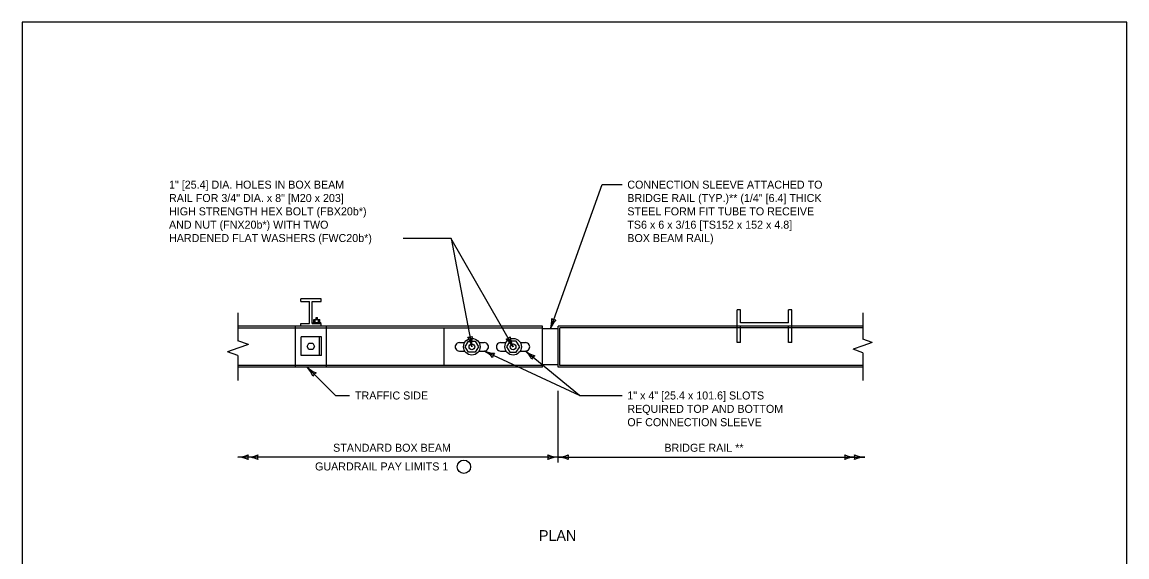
# Model space of a CAD drawing. Extents: x 49991.4 to 50021, y 49987.6 to 50011.4.
# Drawn here: x 50000.34 to 50008.61, y 50007.26 to 50011.26 of the extents above; entities that cross this region are included whole.
import ezdxf

# ---------------------------------------------------------------- set-up
doc = ezdxf.new("R2010")
doc.units = 0
for name, color, linetype in [('Level 1', 7, 'Continuous'), ('Level 2', 7, 'Continuous'), ('Level 3', 7, 'Continuous'), ('Level 4', 7, 'Continuous'), ('Level 6', 7, 'Continuous')]:
    doc.layers.add(name, color=color, linetype=linetype)

msp = doc.modelspace()

# ---------------------------------------------------------------- linework, layer by layer
at = {"layer": 'Level 1'}
for p, q in [((50002.5774, 50009.1903), (50002.4235, 50009.1903)), ((50002.4235, 50009.1702), (50002.4235, 50009.1903)), ((50002.4235, 50009.1702), (50002.4895, 50009.1702)), ((50002.4895, 50009.0047), (50002.4895, 50009.1702)), ((50002.5104, 50009.0047), (50002.5104, 50009.1702)), ((50002.5104, 50009.1702), (50002.5774, 50009.1702)), ((50002.5774, 50009.1702), (50002.5774, 50009.1903)), ((50005.6941, 50008.9846), (50005.6941, 50009.1075)), ((50005.7186, 50009.1075), (50005.6941, 50009.1075)), ((50005.7186, 50009.0095), (50005.7186, 50009.1075)), ((50006.0786, 50009.0095), (50006.0786, 50009.1075)), ((50006.103, 50009.1075), (50006.0786, 50009.1075)), ((50006.103, 50008.9846), (50006.103, 50009.1075)), ((50004.2346, 50008.9846), (50001.9531, 50008.9846)), ((50002.4235, 50009.0047), (50002.4895, 50009.0047)), ((50002.4235, 50008.9846), (50002.4235, 50009.0047)), ((50002.5104, 50009.0047), (50002.5774, 50009.0047)), ((50002.5161, 50009.0047), (50002.5161, 50009.0128)), ((50002.5161, 50009.0128), (50002.5741, 50009.0128)), ((50002.523, 50009.0338), (50002.5656, 50009.0338)), ((50002.523, 50009.0128), (50002.523, 50009.0338)), ((50002.533, 50009.0128), (50002.533, 50009.0338)), ((50002.5387, 50009.049), (50002.5504, 50009.049)), ((50002.5387, 50009.0338), (50002.5387, 50009.049)), ((50002.5504, 50009.0338), (50002.5504, 50009.049)), ((50002.5564, 50009.0128), (50002.5564, 50009.0338)), ((50002.5656, 50009.0128), (50002.5656, 50009.0338)), ((50002.5741, 50009.0047), (50002.5741, 50009.0128)), ((50002.5774, 50008.9846), (50002.5774, 50009.0047)), ((50004.2346, 50008.6768), (50004.2346, 50008.9846)), ((50004.3525, 50008.6768), (50004.3539, 50008.9846)), ((50006.6354, 50008.9846), (50004.3539, 50008.9846)), ((50006.0786, 50009.0095), (50005.7186, 50009.0095)), ((50002.5788, 50008.9059), (50002.4264, 50008.9059)), ((50002.4264, 50008.7655), (50002.4264, 50008.9059)), ((50002.5635, 50008.7655), (50002.5635, 50008.9059)), ((50002.5788, 50008.7655), (50002.5788, 50008.9059)), ((50004.3539, 50008.966), (50004.2346, 50008.966)), ((50002.5788, 50008.7655), (50002.4264, 50008.7655)), ((50004.2346, 50008.6768), (50001.9531, 50008.6768)), ((50004.3526, 50008.6953), (50004.2346, 50008.6953)), ((50006.6354, 50008.6768), (50004.3525, 50008.6768))]:
    msp.add_line(p, q, dxfattribs=at)
for points in [[(50008.6146, 50011.2628), (50000.3356, 50011.2628), (50000.3356, 50000.0624), (50008.6146, 50000.0624)], [(50002.5146, 50008.8109), (50002.4852, 50008.8109), (50002.4729, 50008.8331), (50002.4852, 50008.857), (50002.5146, 50008.857), (50002.5272, 50008.8331)], [(50003.7297, 50008.8724), (50003.7557, 50008.8304), (50003.7297, 50008.7898), (50003.6816, 50008.7898), (50003.6556, 50008.8304), (50003.6816, 50008.8724)], [(50003.9895, 50008.8724), (50003.9645, 50008.8304), (50003.9895, 50008.7898), (50004.039, 50008.7898), (50004.0645, 50008.8304), (50004.039, 50008.8724)]]:
    msp.add_lwpolyline(points, close=True, dxfattribs=at)
for centre, radius in [((50003.7057, 50008.8306), 0.0619), ((50004.0154, 50008.8306), 0.0619), ((50003.7061, 50008.8302), 0.0214), ((50004.015, 50008.8302), 0.0214)]:
    msp.add_circle(centre, radius, dxfattribs=at)
at = {"layer": 'Level 2'}
msp.add_circle((50003.6464, 50007.9312), 0.05, dxfattribs=at)
at = {"layer": 'Level 3'}
for p, q in [((50004.2943, 50008.966), (50004.6826, 50010.045)), ((50004.6826, 50010.045), (50004.8311, 50010.045)), ((50003.191, 50009.645), (50003.5487, 50009.645)), ((50004.015, 50008.8302), (50003.5491, 50009.6448)), ((50003.5501, 50009.6421), (50003.7061, 50008.8302)), ((50004.5119, 50008.4655), (50003.799, 50008.7984)), ((50004.5119, 50008.4655), (50004.1074, 50008.7984)), ((50002.4723, 50008.6768), (50002.6847, 50008.4655)), ((50004.3525, 50007.964), (50004.3525, 50008.4999)), ((50002.6847, 50008.4655), (50002.7902, 50008.4655)), ((50004.5119, 50008.4655), (50004.8311, 50008.4655)), ((50004.3525, 50008.004), (50001.9531, 50008.004)), ((50004.3525, 50008.004), (50006.6505, 50008.004))]:
    msp.add_line(p, q, dxfattribs=at)
for centre, radius, start, end in [((50004.0714, 50009.034), 0.233, 343.03502, 2.28487), ((50004.5002, 50008.8822), 0.2223, 137.66372, 157.84723), ((50004.3377, 50009.0866), 0.0548, 232.34653, 268.06889), ((50003.6819, 50008.9561), 0.0548, 263.01724, 298.7396), ((50003.4798, 50008.775), 0.233, 13.70573, 32.95558), ((50003.926, 50008.8631), 0.2223, 168.33443, 188.51794), ((50003.9513, 50008.9415), 0.0548, 281.90701, 317.62937), ((50003.8187, 50008.7047), 0.233, 32.5955, 51.84535), ((50004.2124, 50008.9325), 0.2223, 187.2242, 207.40771), ((50003.6968, 50008.601), 0.2223, 42.42587, 62.60938), ((50003.8871, 50009.0141), 0.233, 247.79717, 267.04702), ((50003.6968, 50008.601), 0.2223, 42.42587, 62.60938), ((50003.8871, 50009.0141), 0.233, 247.79717, 267.04702), ((50003.9152, 50008.7441), 0.0548, 137.10868, 172.83104), ((50003.9152, 50008.7441), 0.0548, 137.10868, 172.83104), ((50003.9592, 50008.6327), 0.2223, 28.00079, 48.1843), ((50004.2464, 50008.9854), 0.233, 233.37209, 252.62194), ((50004.2064, 50008.7169), 0.0548, 122.6836, 158.40596), ((50002.3091, 50008.5258), 0.2223, 22.61055, 42.79406), ((50002.6282, 50008.8499), 0.233, 227.98185, 247.2317), ((50002.5632, 50008.5864), 0.0548, 117.29336, 153.01572), ((50001.9416, 50008.2367), 0.233, 272.82731, 292.07716), ((50001.9439, 50007.7819), 0.2223, 67.45601, 87.63952), ((50002.015, 50008.2367), 0.233, 272.82731, 292.07716), ((50002.0813, 50008.004), 0.0548, 162.13882, 197.86118), ((50002.0174, 50007.7819), 0.2223, 67.45601, 87.63952), ((50002.1548, 50008.004), 0.0548, 162.13882, 197.86118), ((50004.3617, 50008.2261), 0.2223, 247.45601, 267.63952), ((50004.2243, 50008.004), 0.0548, 342.13882, 17.86118), ((50004.364, 50007.7713), 0.233, 92.82731, 112.07716), ((50004.3411, 50008.2367), 0.233, 272.82731, 292.07716), ((50004.3434, 50007.7819), 0.2223, 67.45601, 87.63952), ((50004.4808, 50008.004), 0.0548, 162.13882, 197.86118), ((50006.5862, 50008.2261), 0.2223, 247.45601, 267.63952), ((50006.4489, 50008.004), 0.0548, 342.13882, 17.86118), ((50006.5886, 50007.7713), 0.233, 92.82731, 112.07716), ((50006.6597, 50008.2261), 0.2223, 247.45601, 267.63952), ((50006.5223, 50008.004), 0.0548, 342.13882, 17.86118), ((50006.662, 50007.7713), 0.233, 92.82731, 112.07716)]:
    msp.add_arc(centre, radius, start, end, dxfattribs=at)
at = {"layer": 'Level 4'}
for p, q in [((50004.2346, 50008.9695), (50001.9531, 50008.9695)), ((50002.3841, 50008.6768), (50002.3841, 50008.9846)), ((50002.6157, 50008.6768), (50002.6157, 50008.9846)), ((50003.4984, 50008.6909), (50003.4984, 50008.9695)), ((50006.6354, 50008.9726), (50004.3657, 50008.9726)), ((50004.3657, 50008.6894), (50004.3657, 50008.9726)), ((50005.6941, 50008.8625), (50005.6941, 50008.9846)), ((50005.7186, 50008.8625), (50005.7186, 50008.9846)), ((50006.0786, 50008.8625), (50006.0786, 50008.9846)), ((50006.103, 50008.8625), (50006.103, 50008.9846)), ((50003.6123, 50008.862), (50003.6523, 50008.862)), ((50003.759, 50008.862), (50003.799, 50008.862)), ((50003.9212, 50008.862), (50003.9621, 50008.862)), ((50004.0688, 50008.862), (50004.1079, 50008.862)), ((50005.7186, 50008.8625), (50005.6941, 50008.8625)), ((50006.103, 50008.8625), (50006.0786, 50008.8625)), ((50003.6128, 50008.7984), (50003.6528, 50008.7984)), ((50003.7586, 50008.7984), (50003.7986, 50008.7984)), ((50003.9216, 50008.7984), (50003.9625, 50008.7984)), ((50004.0683, 50008.7984), (50004.1074, 50008.7984)), ((50004.2346, 50008.6909), (50001.9531, 50008.6909)), ((50006.6354, 50008.6894), (50004.3657, 50008.6894))]:
    msp.add_line(p, q, dxfattribs=at)
for centre, start, end in [((50003.6123, 50008.8302), 89.99726, 270.82043), ((50003.799, 50008.8302), 269.17957, 90.00274), ((50003.9212, 50008.8302), 89.99726, 270.82043), ((50004.1079, 50008.8302), 269.17957, 90.00274)]:
    msp.add_arc(centre, 0.0318, start, end, dxfattribs=at)
at = {"layer": 'Level 6'}
for p, q in [((50001.9531, 50009.0846), (50001.9531, 50008.876)), ((50006.6354, 50009.0846), (50006.6354, 50008.887)), ((50006.7065, 50008.8619), (50006.6354, 50008.887)), ((50001.9531, 50008.8202), (50001.8741, 50008.7922)), ((50002.032, 50008.8481), (50001.9531, 50008.876)), ((50002.032, 50008.8481), (50001.9531, 50008.8202)), ((50006.6354, 50008.8367), (50006.5643, 50008.8114)), ((50006.6354, 50008.7863), (50006.5643, 50008.8114)), ((50006.7065, 50008.8619), (50006.6354, 50008.8367)), ((50001.9531, 50008.7641), (50001.8741, 50008.7922)), ((50001.9531, 50008.7641), (50001.9531, 50008.5768)), ((50006.6354, 50008.7863), (50006.6354, 50008.5768))]:
    msp.add_line(p, q, dxfattribs=at)

# ---------------------------------------------------------------- texts
at = {"layer": 'Level 2'}
for s, height, p in [('1" [25.4] DIA. HOLES IN BOX BEAM', 0.06, (50001.4366, 50010.015)), ('CONNECTION SLEEVE ATTACHED TO ', 0.06, (50004.871, 50010.015)), ('RAIL FOR 3/4" DIA. x 8" [M20 x 203]', 0.06, (50001.4366, 50009.915)), ('BRIDGE RAIL (TYP.)** (1/4" [6.4] THICK', 0.06, (50004.871, 50009.915)), ('HIGH STRENGTH HEX BOLT (FBX20b*)', 0.06, (50001.4366, 50009.815)), ('STEEL FORM FIT TUBE TO RECEIVE', 0.06, (50004.871, 50009.815)), ('AND NUT (FNX20b*) WITH TWO ', 0.06, (50001.4366, 50009.715)), ('TS6 x 6 x 3/16 [TS152 x 152 x 4.8] ', 0.06, (50004.871, 50009.715)), ('HARDENED FLAT WASHERS (FWC20b*)', 0.06, (50001.4366, 50009.615)), ('BOX BEAM RAIL)', 0.06, (50004.871, 50009.615)), ('TRAFFIC SIDE', 0.06, (50002.8301, 50008.4355)), ('1" x 4" [25.4 x 101.6] SLOTS', 0.06, (50004.871, 50008.4355)), ('REQUIRED TOP AND BOTTOM', 0.06, (50004.871, 50008.3355)), ('OF CONNECTION SLEEVE', 0.06, (50004.871, 50008.2355)), ('STANDARD BOX BEAM', 0.06, (50002.6664, 50008.044)), ('BRIDGE RAIL **', 0.06, (50005.1487, 50008.044)), ('GUARDRAIL PAY LIMITS 1', 0.06, (50002.5308, 50007.904)), ('PLAN', 0.08, (50004.2088, 50007.3766))]:
    msp.add_text(s, height=height, dxfattribs=at).set_placement(p)

doc.saveas('drawing.dxf')
